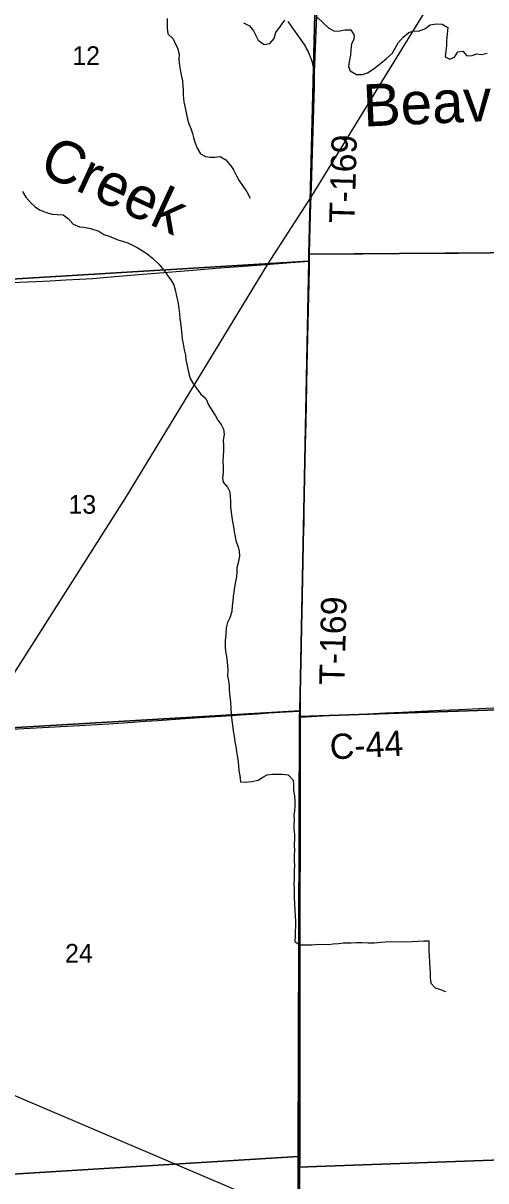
# Model space of a CAD drawing. Extents: x 0 to 34, y 0 to 22.
# Drawn here: x 6.439 to 6.958, y 18.765 to 20.064 of the extents above; entities that cross this region are included whole.
import ezdxf

# ---------------------------------------------------------------- set-up
doc = ezdxf.new("R2010")
doc.units = 0
for name, color, linetype in [('GM_X_Corporation', 7, 'Continuous'), ('GM_X_County_Road', 7, 'Continuous'), ('GM_X_County_Road_Text', 7, 'Continuous'), ('GM_X_Minor_River', 7, 'Continuous'), ('GM_X_Minor_River_Text', 7, 'Continuous'), ('GM_X_Rail_Line', 7, 'Continuous'), ('GM_X_Section_Text', 7, 'Continuous'), ('GM_X_Township_Road', 7, 'Continuous'), ('GM_X_Township_Road_Text', 7, 'Continuous'), ('SH_Text', 7, 'Continuous')]:
    doc.layers.add(name, color=color, linetype=linetype)

msp = doc.modelspace()

# ---------------------------------------------------------------- linework, layer by layer
at = {"layer": 'GM_X_Corporation'}
msp.add_lwpolyline([(6.7779, 20.3067), (6.7656, 20.009), (6.7656, 20.0086), (6.7657, 20.0024), (6.7656, 19.9922), (6.7653, 19.981), (6.7645, 19.9558), (6.7637, 19.9304), (6.7634, 19.9193), (6.7625, 19.8922), (6.7612, 19.85), (6.7605, 19.8211), (6.7602, 19.8055), (6.7601, 19.8003), (6.76, 19.7975), (6.7599, 19.7879), (6.7589, 19.7425), (6.7583, 19.7118), (6.7579, 19.6954), (6.7575, 19.6789), (6.7562, 19.616), (6.7557, 19.5915), (6.7541, 19.526), (6.7539, 19.5045), (6.7534, 19.4831), (6.7529, 19.4601), (6.7521, 19.4209), (6.7514, 19.3861), (6.7505, 19.346), (6.7501, 19.3227), (6.7499, 19.3072), (6.7498, 19.296), (6.7499, 19.2921), (6.7499, 19.2895), (6.7498, 19.2874), (6.7498, 19.2855), (6.7498, 19.2753), (6.7493, 18.6176)], dxfattribs=at)
msp.add_lwpolyline([(6.7779, 20.3067), (6.7656, 20.009), (6.7656, 20.0086), (6.7657, 20.0024), (6.7656, 19.9922), (6.7653, 19.981), (6.7645, 19.9558), (6.7637, 19.9304), (6.7634, 19.9193), (6.7625, 19.8922), (6.7612, 19.85), (6.7605, 19.8211), (6.7602, 19.8055), (6.7601, 19.8003), (6.76, 19.7975), (6.7599, 19.7879), (6.7589, 19.7425), (6.7583, 19.7118), (6.7579, 19.6954), (6.7575, 19.6789), (6.7562, 19.616), (6.7557, 19.5915), (6.7541, 19.526), (6.7539, 19.5045), (6.7534, 19.4831), (6.7529, 19.4601), (6.7521, 19.4209), (6.7514, 19.3861), (6.7505, 19.346), (6.7501, 19.3227), (6.7499, 19.3072), (6.7498, 19.296), (6.7499, 19.2921), (6.7499, 19.2895), (6.7498, 19.2874), (6.7498, 19.2855), (6.7498, 19.2753), (6.7493, 18.6176)], dxfattribs=at)
for points in [[(6.7723, 20.3107), (7.2741, 20.3108), (7.2691, 19.8089), (6.7597, 19.805), (6.7719, 20.2989)], [(6.254, 20.2716), (6.7719, 20.2989), (6.7597, 19.805), (6.7595, 19.7972), (6.2587, 19.7668)], [(6.7597, 19.805), (7.2691, 19.8089), (7.2707, 19.3035), (6.7493, 19.286), (6.7494, 19.2921), (6.7595, 19.7972)], [(6.2587, 19.7668), (6.7595, 19.7972), (6.7494, 19.2921), (6.2596, 19.2633)], [(6.7493, 19.286), (7.2707, 19.3035), (7.2769, 18.799), (6.7477, 18.7799), (6.7476, 18.7919)], [(6.7494, 19.2921), (6.7493, 19.286), (6.7476, 18.7919), (6.2515, 18.761), (6.2596, 19.2633)], [(6.7477, 18.7799), (7.2769, 18.799), (7.288, 18.294), (6.7481, 18.2831)], [(6.7476, 18.7919), (6.7477, 18.7799), (6.7481, 18.2831), (6.2454, 18.2601), (6.2515, 18.761)]]:
    msp.add_lwpolyline(points, close=True, dxfattribs=at)
at = {"layer": 'GM_X_County_Road'}
for points in [[(6.7499, 19.2852), (6.7625, 19.2859), (6.7814, 19.2869), (6.8088, 19.2882), (6.8255, 19.289), (6.8457, 19.2899), (6.8647, 19.2909), (6.8932, 19.2923), (6.9079, 19.293), (6.9283, 19.2939), (6.9507, 19.295), (6.9752, 19.2961), (6.9976, 19.2972), (7.018, 19.2982), (7.0493, 19.299), (7.0663, 19.2995), (7.0848, 19.3), (7.1373, 19.3014), (7.1711, 19.3023), (7.2222, 19.3037), (7.2563, 19.3043), (7.2718, 19.3046)], [(6.4116, 19.2708), (6.447, 19.2727), (6.509, 19.2763), (6.5354, 19.2778), (6.5618, 19.2796), (6.5764, 19.2806), (6.5903, 19.2816), (6.6154, 19.2832), (6.6424, 19.285), (6.6613, 19.2863), (6.6828, 19.2877), (6.7015, 19.289), (6.7146, 19.2899), (6.7274, 19.2908), (6.7341, 19.2912), (6.7416, 19.2916), (6.7469, 19.2918), (6.75, 19.2918)], [(6.75, 19.2918), (6.75, 19.2892), (6.7499, 19.2871), (6.7499, 19.2852)]]:
    msp.add_lwpolyline(points, dxfattribs=at)
at = {"layer": 'GM_X_Minor_River'}
for points in [[(6.7693, 20.0707), (6.7821, 20.0588), (6.7878, 20.0558), (6.7927, 20.0556), (6.8001, 20.057), (6.8069, 20.057), (6.8106, 20.0511), (6.8102, 20.046), (6.8076, 20.0411), (6.8068, 20.0346), (6.8065, 20.0284), (6.8052, 20.0233), (6.8042, 20.0159), (6.8062, 20.0109), (6.8132, 20.0067), (6.82, 20.0067), (6.8255, 20.0085), (6.8331, 20.0136), (6.8403, 20.0196), (6.8468, 20.0247), (6.8531, 20.0304), (6.8561, 20.0355), (6.86, 20.0423), (6.8655, 20.0487), (6.8719, 20.054), (6.8778, 20.0558), (6.8827, 20.0554), (6.8899, 20.0582), (6.896, 20.0626), (6.9025, 20.0635), (6.9093, 20.0634), (6.9157, 20.0594), (6.9149, 20.0522), (6.9143, 20.0448), (6.9142, 20.0395), (6.9134, 20.0329), (6.9128, 20.0266), (6.9179, 20.0239), (6.923, 20.0262), (6.9269, 20.0324), (6.9325, 20.0331), (6.9371, 20.0276), (6.9429, 20.028), (6.9482, 20.03), (6.9531, 20.0294), (6.9596, 20.0307)], [(6.6008, 20.0697), (6.6007, 20.064), (6.6007, 20.0589), (6.6014, 20.0523), (6.6073, 20.0468), (6.6097, 20.0414), (6.6123, 20.0367), (6.614, 20.0296), (6.6139, 20.0236), (6.6146, 20.0167), (6.6156, 20.0103), (6.6168, 20.0044), (6.6178, 19.9997), (6.6183, 19.9936), (6.6186, 19.9889), (6.6188, 19.9835), (6.6195, 19.9761), (6.6208, 19.9693), (6.6219, 19.9636), (6.6234, 19.9566), (6.6249, 19.9513), (6.6273, 19.9461), (6.629, 19.9406), (6.6303, 19.9359), (6.6319, 19.9307), (6.6345, 19.9239), (6.6379, 19.9178), (6.6438, 19.9148), (6.649, 19.9138), (6.6543, 19.9141), (6.6602, 19.9147), (6.6666, 19.9108), (6.6723, 19.9044), (6.6751, 19.8996), (6.6784, 19.8929), (6.6811, 19.8882), (6.6901, 19.8749), (6.6938, 19.868)], [(6.6864, 20.0649), (6.693, 20.0613), (6.6977, 20.0559), (6.6998, 20.0512), (6.7028, 20.0453), (6.7096, 20.0403), (6.7158, 20.0416), (6.7209, 20.0472), (6.7227, 20.0539), (6.7278, 20.0611), (6.7328, 20.0679)], [(6.4383, 19.8753), (6.4422, 19.8692), (6.4478, 19.8626), (6.4527, 19.858), (6.4576, 19.8549), (6.4648, 19.852), (6.4718, 19.8501), (6.4771, 19.8497), (6.4841, 19.8493), (6.4894, 19.8451), (6.4952, 19.8388), (6.5022, 19.8357), (6.5073, 19.8353), (6.5148, 19.8337), (6.5241, 19.8307), (6.5296, 19.8272), (6.5356, 19.8251), (6.5454, 19.8212), (6.5507, 19.8197), (6.5564, 19.8176), (6.5618, 19.8153), (6.5669, 19.8124), (6.573, 19.8086), (6.5779, 19.8059), (6.5844, 19.8005), (6.5914, 19.7937), (6.5969, 19.7872), (6.6012, 19.7811), (6.6047, 19.7762), (6.6081, 19.7705), (6.6096, 19.7649), (6.6109, 19.7598), (6.6118, 19.7547), (6.6129, 19.7498), (6.6138, 19.7441), (6.6144, 19.7382), (6.6149, 19.7329), (6.6158, 19.7279), (6.6165, 19.7215), (6.6172, 19.7143), (6.6176, 19.7095)], [(6.6176, 19.7095), (6.6187, 19.7044), (6.6198, 19.6976), (6.6213, 19.6917), (6.6218, 19.6864), (6.6229, 19.6816), (6.624, 19.6761), (6.6249, 19.671), (6.6264, 19.6653), (6.6302, 19.659), (6.635, 19.6525), (6.6384, 19.6478), (6.6441, 19.643), (6.6472, 19.6358), (6.6508, 19.6297), (6.6549, 19.6234), (6.6577, 19.6185), (6.6613, 19.6137), (6.6639, 19.6086), (6.6648, 19.6029), (6.6637, 19.5959), (6.6638, 19.5902), (6.664, 19.5841), (6.6636, 19.5788), (6.6631, 19.572), (6.6635, 19.5665), (6.6636, 19.5596), (6.6627, 19.554), (6.6636, 19.5492), (6.6683, 19.5435), (6.6711, 19.5382), (6.6714, 19.5331), (6.6716, 19.5276), (6.6717, 19.5209), (6.6725, 19.5154), (6.6734, 19.5099), (6.6741, 19.5044), (6.675, 19.4991), (6.6757, 19.4932), (6.677, 19.4881), (6.6779, 19.4833), (6.6802, 19.4763), (6.6815, 19.4714), (6.682, 19.4659), (6.6803, 19.4585), (6.6789, 19.453), (6.6789, 19.4479), (6.6783, 19.4429), (6.6775, 19.4376), (6.6763, 19.4312), (6.6755, 19.4257), (6.6749, 19.4208), (6.6743, 19.4157), (6.6737, 19.41), (6.6731, 19.4039), (6.671, 19.3967), (6.6685, 19.3916), (6.6668, 19.3854), (6.6664, 19.3787), (6.6657, 19.371), (6.6657, 19.3639), (6.6662, 19.3588), (6.6673, 19.3533), (6.6681, 19.3472), (6.6684, 19.3425), (6.6686, 19.3378), (6.6685, 19.3317), (6.6695, 19.3262), (6.6702, 19.3203), (6.6703, 19.3154), (6.6711, 19.3082), (6.6718, 19.3019), (6.6723, 19.2945), (6.6725, 19.2888), (6.6732, 19.2816), (6.6739, 19.2763), (6.6748, 19.27), (6.6759, 19.264), (6.6768, 19.2573), (6.6777, 19.2522), (6.6786, 19.2465), (6.6797, 19.24), (6.6803, 19.2351), (6.6806, 19.23), (6.6812, 19.2251), (6.6824, 19.2194), (6.683, 19.2127), (6.6887, 19.2121), (6.6957, 19.213), (6.7027, 19.2145), (6.7082, 19.2179), (6.7129, 19.2203), (6.718, 19.2211), (6.7246, 19.2212), (6.7298, 19.221), (6.7366, 19.2204), (6.742, 19.2145), (6.7424, 19.2092), (6.7425, 19.2029), (6.7434, 19.1968), (6.7438, 19.1913)], [(6.7438, 19.1913), (6.7441, 19.186), (6.7435, 19.1801), (6.7429, 19.175), (6.7433, 19.1699), (6.743, 19.1642), (6.743, 19.1593), (6.7435, 19.1534), (6.7435, 19.1487), (6.7433, 19.142), (6.7434, 19.1352), (6.7432, 19.1305), (6.7432, 19.1236), (6.7435, 19.1185), (6.7433, 19.1136), (6.7433, 19.1075), (6.7431, 19.1026), (6.743, 19.0978), (6.7432, 19.0923), (6.7432, 19.0874), (6.7433, 19.0823), (6.7435, 19.0759), (6.744, 19.0686), (6.7443, 19.0618), (6.7447, 19.0565), (6.7446, 19.0506), (6.7442, 19.044), (6.7442, 19.0393), (6.744, 19.0332), (6.7494, 19.0296), (6.7555, 19.0297), (6.7634, 19.0295), (6.771, 19.0302), (6.7822, 19.0301), (6.7871, 19.0307), (6.793, 19.0312), (6.7984, 19.0317), (6.807, 19.0319), (6.8132, 19.0322), (6.8191, 19.032), (6.8264, 19.0318), (6.8332, 19.0319), (6.8401, 19.0326), (6.8452, 19.033), (6.8522, 19.0331), (6.858, 19.0329), (6.8639, 19.0331), (6.8696, 19.033), (6.8753, 19.0332), (6.8821, 19.0335), (6.8887, 19.0339), (6.8944, 19.0339), (6.8945, 19.0272), (6.8945, 19.0221), (6.8948, 19.0174), (6.895, 19.0101), (6.8953, 19.0033), (6.896, 18.9984), (6.896, 18.9927), (6.8964, 18.9866), (6.9014, 18.9813), (6.9063, 18.9797), (6.9131, 18.9772)]]:
    msp.add_lwpolyline(points, dxfattribs=at)
at = {"layer": 'GM_X_Rail_Line'}
msp.add_lwpolyline([(4.8309, 16.8143), (4.9535, 17.0036), (5.121, 17.2554), (5.3168, 17.5533), (5.4525, 17.7592), (5.5868, 17.9828), (5.7483, 18.2398), (5.9042, 18.4974), (6.0213, 18.6826), (6.1366, 18.8725), (6.2288, 19.0173), (6.3431, 19.201), (6.3879, 19.2703), (6.555, 19.533), (6.7138, 19.7939), (6.7635, 19.8708), (6.8447, 20.0035), (6.9408, 20.16), (7.0326, 20.3087), (7.173, 20.5257), (7.1992, 20.5654)], dxfattribs=at)
at = {"layer": 'GM_X_Township_Road'}
for points in [[(6.765, 20.0148), (6.7649, 20.0154), (6.7646, 20.0166), (6.7643, 20.0181), (6.7637, 20.0202), (6.763, 20.0225), (6.7622, 20.0249), (6.7613, 20.0271), (6.7604, 20.0293), (6.7594, 20.0317), (6.7584, 20.0336), (6.7571, 20.0361), (6.7558, 20.0385), (6.7547, 20.0404), (6.753, 20.0431), (6.7511, 20.0458), (6.7363, 20.0661)], [(6.7603, 19.8052), (6.7606, 19.8208), (6.7614, 19.8497), (6.7626, 19.892), (6.7635, 19.919), (6.7638, 19.9302), (6.7646, 19.9556), (6.7654, 19.9807), (6.7657, 19.9919), (6.7658, 20.0021), (6.7657, 20.0083), (6.7657, 20.0087)], [(6.7657, 20.0087), (6.7655, 20.0117), (6.7652, 20.0136), (6.765, 20.0148)], [(6.7601, 19.7973), (6.7602, 19.8001), (6.7603, 19.8052)], [(6.7603, 19.8052), (6.7672, 19.8053), (6.7746, 19.8053), (6.7811, 19.8054), (6.7876, 19.8054), (6.7946, 19.8053), (6.798, 19.8055), (6.8011, 19.8054), (6.8054, 19.8055), (6.8104, 19.8055), (6.8172, 19.8055), (6.8203, 19.8056), (6.8337, 19.8057), (6.8402, 19.8057), (6.8492, 19.8058), (6.8532, 19.8058), (6.8588, 19.8059), (6.8684, 19.806), (6.8824, 19.806), (6.889, 19.8061), (6.8955, 19.8061), (6.9275, 19.8063), (6.9508, 19.8065), (6.9918, 19.807)], [(6.26, 19.7668), (6.2693, 19.7672), (6.2907, 19.768), (6.3236, 19.7694), (6.3789, 19.7716), (6.3976, 19.7722), (6.4532, 19.7745), (6.4693, 19.7752), (6.487, 19.7761), (6.5022, 19.777), (6.5174, 19.7779), (6.5332, 19.7792), (6.5595, 19.7814), (6.6295, 19.7871), (6.6602, 19.7896), (6.6915, 19.7921), (6.7163, 19.7939), (6.7442, 19.7959), (6.7601, 19.7973)], [(6.75, 19.2918), (6.7499, 19.2957), (6.75, 19.3069), (6.7502, 19.3225), (6.7506, 19.3458), (6.7515, 19.3858), (6.7522, 19.4206), (6.7531, 19.4598), (6.7535, 19.4828), (6.754, 19.5042), (6.7543, 19.5257), (6.7558, 19.5913), (6.7563, 19.6157), (6.7576, 19.6786), (6.758, 19.6951), (6.7584, 19.7115), (6.759, 19.7422), (6.76, 19.7876), (6.7601, 19.7973)], [(6.7499, 19.2852), (6.7499, 19.2871), (6.75, 19.2892), (6.75, 19.2918)], [(6.7487, 18.7439), (6.7489, 18.7936), (6.749, 18.8309), (6.7491, 18.876), (6.7491, 18.8992), (6.7491, 18.9251), (6.7491, 18.9443), (6.7491, 18.9649), (6.7491, 19.0109), (6.7493, 19.0513), (6.7493, 19.0805), (6.7493, 19.1097), (6.7495, 19.1473), (6.7495, 19.1635), (6.7496, 19.1737), (6.7496, 19.2213), (6.7498, 19.2564), (6.7499, 19.275), (6.7499, 19.2852)]]:
    msp.add_lwpolyline(points, dxfattribs=at)
at = {"layer": 'SH_Text'}
msp.add_lwpolyline([(9.297, 16.882), (2.5966, 20.4971), (9.297, 17.6363)], close=True, dxfattribs=at)

# ---------------------------------------------------------------- texts
at = {"layer": 'GM_X_County_Road_Text'}
msp.add_text('C-44', height=0.02841, rotation=3.0695, dxfattribs=at).set_placement((6.7839, 19.2376))
at = {"layer": 'GM_X_Minor_River_Text'}
for s, rotation, p in [('Beaver', 2.5961, (6.8214, 19.9482)), ('Creek', 335.1591, (6.4548, 19.8967))]:
    msp.add_text(s, height=0.04737, rotation=rotation, dxfattribs=at).set_placement(p)
at = {"layer": 'GM_X_Section_Text'}
for s, p in [('12', (6.4942, 20.0175)), ('13', (6.4899, 19.5136)), ('24', (6.4861, 19.0096))]:
    msp.add_text(s, height=0.02093, rotation=0, dxfattribs=at).set_placement(p)
at = {"layer": 'GM_X_Township_Road_Text'}
for rotation, p in [(88.3151, (6.8108, 19.8396)), (88.5957, (6.7996, 19.3211))]:
    msp.add_text('T-169', height=0.02841, rotation=rotation, dxfattribs=at).set_placement(p)

doc.saveas('drawing.dxf')
